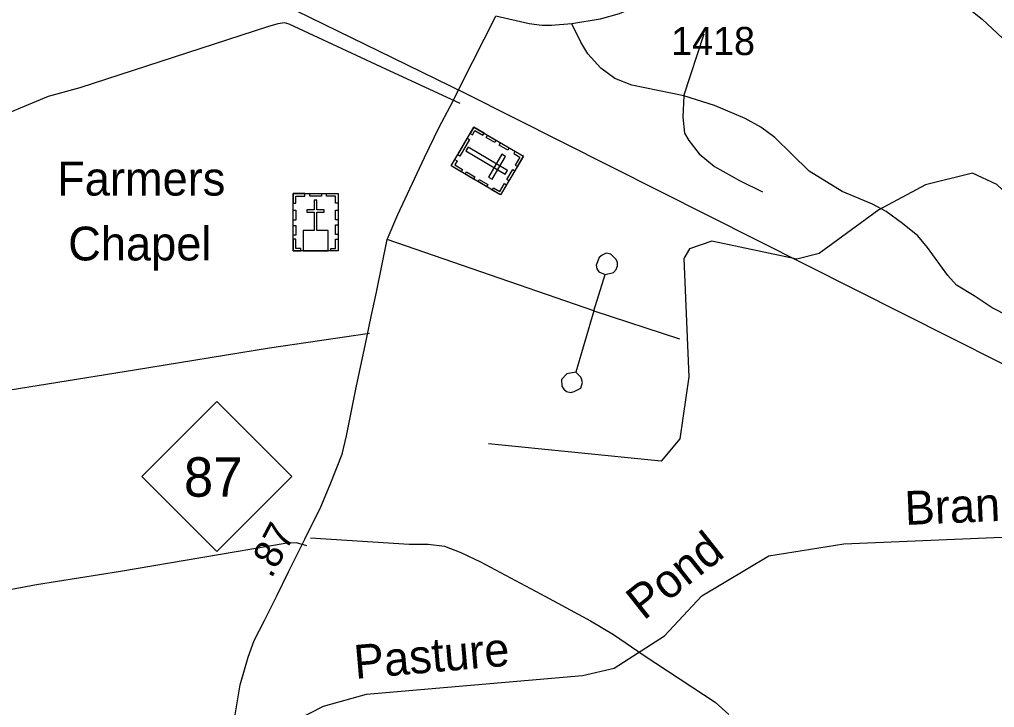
# Model space of a CAD drawing. Extents: x 2225501 to 2309677, y 165449 to 227696.
# Drawn here: x 2257649 to 2261977, y 192432 to 195485 of the extents above; entities that cross this region are included whole.
import ezdxf

# ---------------------------------------------------------------- set-up
doc = ezdxf.new("R2010")
doc.units = 0
for name, color, linetype in [('Black Area Fill Shapes', 7, 'Continuous'), ('E_RDY_CMT_EOP', 7, 'Continuous'), ('Old_Level_3', 7, 'Continuous'), ('Old_Level_33', 7, 'Continuous'), ('Old_Level_46', 7, 'Continuous'), ('Old_Level_50', 7, 'Continuous'), ('P_HYD_Endwall_838_01_48_Dia_Single-Top_CELL', 7, 'Continuous'), ('P_HYD_Junction_Box_with_Slab_Lid_840_31_15_Dia-Top_CELL', 7, 'Continuous'), ('P_HYD_RipRap_Pad_876_02_18in_Outlet_With_Ditch_CELL', 7, 'Continuous'), ('P_HYD_Table_Inlet_Data_CELL', 7, 'Continuous'), ('Prop Mkg Solid Yellow Edge Line', 7, 'Continuous'), ('Prop Support', 7, 'Continuous'), ('Scratch_Level_1', 7, 'Continuous'), ('Scratch_Level_4', 7, 'Continuous'), ('Typical Terminator CELL', 7, 'Continuous')]:
    doc.layers.add(name, color=color, linetype=linetype)

msp = doc.modelspace()

# ---------------------------------------------------------------- linework, layer by layer
at = {"layer": 'Black Area Fill Shapes'}
msp.add_lwpolyline([(2264683.4, 192626.7), (2264435.7, 192743.4), (2264161.2, 192875.9), (2259628.3, 195156.1)], dxfattribs=at)
at = {"layer": 'Old_Level_3'}
for p, q in [((2259308.7, 195312.8), (2257312.8, 196291)), ((2260598.1, 195146), (2260687.8, 195420.6)), ((2259628.3, 195156.1), (2259308.7, 195312.8)), ((2259604.7, 195111.8), (2259253.6, 195274.6)), ((2260198, 194193), (2259281.8, 194509.4)), ((2260198, 194193), (2260248.7, 194353.4)), ((2260198, 194193), (2260118.1, 193920.5)), ((2260198, 194193), (2260578.9, 194068.2))]:
    msp.add_line(p, q, dxfattribs=at)
for points in [[(2259253.6, 195274.6), (2258846.1, 195463.5), (2258826.1, 195469.5), (2258796.2, 195465), (2258750.3, 195452.7), (2257916.9, 195182.1), (2257777.1, 195143), (2257498.2, 195028.6), (2257448.5, 195012.2), (2257324.9, 194951.2), (2257231.3, 194900.5), (2257191.5, 194886.3), (2257125.4, 194899.7), (2257079.3, 194915.2), (2257051.2, 194929.2), (2257019, 194950.8), (2256991, 194962.5), (2256950.6, 195012.3), (2256883.3, 195197.4)], [(2260598.1, 195146), (2260367.7, 195194.1), (2260291.5, 195223.4), (2260229.2, 195269), (2260172.7, 195332.5), (2260140.3, 195384.1), (2260101.7, 195465.8)], [(2260598.1, 195146), (2260592.9, 195051.9), (2260601.5, 194980), (2260619.7, 194948.2), (2260666.1, 194888.6), (2260734.6, 194833.2), (2260844.9, 194770.1), (2260947.3, 194720.9)], [(2262039.5, 194168.2), (2261967.2, 194205.6), (2261886.7, 194258.9), (2261808.4, 194306.2), (2261770.1, 194349.8), (2261679.1, 194473.1), (2261636.7, 194524.7), (2261568.2, 194580), (2261495.9, 194633.4), (2261435.7, 194665), (2261301.3, 194721.8), (2261154.5, 194812.7), (2261001.4, 194961.4), (2260939.1, 195006.8), (2260870.7, 195046.3), (2260734.2, 195103.2), (2260598.1, 195146)], [(2260248.7, 194353.4), (2260286.5, 194361.7), (2260298.4, 194375.8), (2260304.3, 194391.9), (2260304.2, 194407.9), (2260296.1, 194421.9), (2260273.9, 194443.5), (2260254, 194447.5), (2260236, 194439.2), (2260222, 194429.1), (2260208.4, 194395), (2260212.4, 194379.1), (2260220.6, 194365.2), (2260248.7, 194353.4)], [(2259203.4, 194092.1), (2258759.5, 194026), (2258159.8, 193929.2), (2257560.1, 193832.4), (2257047.4, 193746.9)], [(2260118.1, 193920.5), (2260078.4, 193912.2), (2260054.5, 193888.1), (2260056.7, 193858.1), (2260064.8, 193844.1), (2260076.9, 193834.3), (2260097, 193830.5), (2260110.9, 193834.4), (2260140.7, 193848.8), (2260148.6, 193874.9), (2260144.5, 193890.7), (2260140.3, 193898.6), (2260118.1, 193920.5)], [(2258940.7, 193185.2), (2259378.5, 193157.6), (2259462.9, 193157.6), (2259535.6, 193148.9), (2259608.3, 193119.8), (2259695.5, 193079.1), (2259983.5, 192924.9), (2260184.1, 192817.2), (2260285.9, 192756.1), (2260422.6, 192663), (2260737.8, 192456.1), (2260797.9, 192401.8)], [(2258925, 193149.1), (2258878.8, 193162.8), (2258829, 193160.3), (2258098.2, 193036.4), (2257724.9, 192977.3), (2257329.5, 192902.2), (2257281.6, 192895.8), (2257138.4, 192808.6), (2257104.7, 192774.4), (2257071.3, 192702.1), (2257038.1, 192618), (2256979, 192491.4)]]:
    msp.add_lwpolyline(points, dxfattribs=at)
at = {"layer": 'Old_Level_33'}
msp.add_lwpolyline([(2261244.4, 195917), (2261128.6, 195857.3), (2260311.7, 195510.7), (2260226.7, 195487.1), (2260101.7, 195465.8), (2260011.4, 195458.2), (2259967.8, 195458.6), (2259911.7, 195466.3), (2259763.1, 195500.3)], dxfattribs=at)
at = {"layer": 'Old_Level_46'}
msp.add_lwpolyline([(2260129, 196210.1), (2260182.5, 196202.5), (2260349.2, 196183.2), (2260525.3, 196155.2), (2260707.8, 196126.2), (2260872.5, 196091.5), (2261053.4, 196046.8), (2261232.8, 195983.9), (2261407.6, 195889.4), (2261522.3, 195817.9), (2261757.7, 195618.2), (2261921.5, 195486), (2262216.4, 195210.8), (2262990.7, 194529), (2263196.2, 194348.8), (2263442, 194122.8), (2263721, 193886.9), (2263872.7, 193751), (2263970.5, 193659.8), (2264144.9, 193502.9)], dxfattribs=at)
at = {"layer": 'Old_Level_50'}
msp.add_lwpolyline([(2258595.8, 192338.5), (2258629.6, 192532.4), (2258664.3, 192655.9), (2258691.3, 192729.2), (2258737.6, 192818.2), (2258791.6, 192928.2), (2258843.7, 193034.3), (2258916, 193180), (2258987.4, 193322.8), (2259027.9, 193421.3), (2259081.9, 193556.3), (2259101.2, 193637.4), (2259145.6, 193859.3), (2259184.1, 194038.8), (2259210.2, 194167.1), (2259233.7, 194275.2), (2259281.8, 194509.4), (2259328.8, 194619.8), (2259446.5, 194872.8), (2259510.1, 195004.1), (2259562.2, 195102.5), (2259660.6, 195295.4), (2259763.1, 195500.3)], dxfattribs=at)
at = {"layer": 'P_HYD_Endwall_838_01_48_Dia_Single-Top_CELL'}
for points in [[(2258864.6, 194712.7), (2259063.7, 194712.7), (2259063.8, 194458.1), (2258864.7, 194458)], [(2258864.6, 194669.4), (2258876, 194669.4), (2258876, 194701.6), (2258916.5, 194701.6), (2258916.5, 194712.7), (2258864.6, 194712.7)], [(2258938.7, 194712.7), (2258990.5, 194712.7), (2258990.5, 194701.3), (2258938.7, 194701.3)], [(2259063.8, 194669.4), (2259052.5, 194669.4), (2259052.5, 194701.5), (2259011.9, 194701.5), (2259011.9, 194712.7), (2259063.8, 194712.7)], [(2258907.8, 194458.1), (2259019.9, 194458.1), (2259019.9, 194548.7), (2258969.2, 194548.7), (2258969.1, 194630.2), (2259002.1, 194630.2), (2259002.1, 194641.2), (2258969.1, 194641.2), (2258969.2, 194683.4), (2258957.5, 194683.4), (2258957.5, 194641.2), (2258924.4, 194641.2), (2258924.4, 194630.2), (2258957.5, 194630.2), (2258957.6, 194548.7), (2258907.8, 194548.7)], [(2258864.6, 194595.2), (2258864.6, 194638.5), (2258876, 194638.5), (2258876, 194595.2)], [(2259052.4, 194596.3), (2259052.4, 194639.6), (2259063.8, 194639.6), (2259063.8, 194596.3)], [(2258864.6, 194528), (2258864.6, 194571.3), (2258876, 194571.3), (2258876, 194528)], [(2259052.4, 194530.4), (2259052.4, 194573.7), (2259063.8, 194573.7), (2259063.8, 194530.4)], [(2258897.8, 194458.1), (2258897.8, 194469.6), (2258875.8, 194469.6), (2258875.8, 194510), (2258864.6, 194510), (2258864.6, 194458.1)], [(2259030.7, 194458.1), (2259030.7, 194469.6), (2259052.7, 194469.6), (2259052.6, 194510), (2259063.8, 194510), (2259063.8, 194458.1)]]:
    msp.add_lwpolyline(points, close=True, dxfattribs=at)
at = {"layer": 'P_HYD_Junction_Box_with_Slab_Lid_840_31_15_Dia-Top_CELL'}
msp.add_lwpolyline([(2258192, 193457.3), (2258525, 193790.3), (2258858, 193457.3), (2258525, 193124.3)], close=True, dxfattribs=at)
at = {"layer": 'Prop Mkg Solid Yellow Edge Line'}
for points in [[(2259886, 194877.9), (2259784.9, 194706.4), (2259565.5, 194835.7), (2259666.7, 195007.2)], [(2259649.9, 194978.7), (2259659.8, 194972.9), (2259671, 194991.8), (2259705.8, 194971.3), (2259711.4, 194980.9), (2259666.7, 195007.2)], [(2259647.4, 194951.9), (2259604.3, 194878.8), (2259594.5, 194884.6), (2259637.6, 194957.7)], [(2259726.9, 194971.7), (2259764.2, 194949.7), (2259758.5, 194939.9), (2259721.1, 194961.9)], [(2259805.4, 194798.9), (2259814.9, 194815), (2259640.2, 194917.9), (2259630.7, 194901.9)], [(2259784.8, 194937.6), (2259822.1, 194915.6), (2259816.4, 194905.8), (2259779, 194927.8)], [(2259806.7, 194877.3), (2259790.6, 194886.8), (2259730.8, 194785.4), (2259746.9, 194775.9)], [(2259848.7, 194899.9), (2259842.9, 194890.1), (2259870.7, 194873.8), (2259850.1, 194838.8), (2259859.6, 194833.2), (2259886, 194877.9)], [(2259582.4, 194864.3), (2259592.3, 194858.4), (2259581.1, 194839.5), (2259615.9, 194819), (2259610.3, 194809.4), (2259565.5, 194835.7)], [(2259633.6, 194808.8), (2259670.9, 194786.8), (2259665.1, 194777), (2259627.8, 194799)], [(2259848.4, 194814.1), (2259822, 194769.5), (2259812.2, 194775.2), (2259838.6, 194819.9)], [(2259690.3, 194775.3), (2259727.7, 194753.3), (2259721.9, 194743.5), (2259684.6, 194765.5)], [(2259747.5, 194728.4), (2259753.3, 194738.1), (2259781, 194721.8), (2259801.6, 194756.7), (2259811.2, 194751.1), (2259784.8, 194706.4)]]:
    msp.add_lwpolyline(points, close=True, dxfattribs=at)
at = {"layer": 'Prop Support'}
msp.add_lwpolyline([(2262848.3, 193750.5), (2262844.9, 193767.8), (2262667.7, 194066.5), (2262448.7, 194316.8), (2261986.7, 194752.2), (2261878.7, 194803.5), (2261670.8, 194751.8), (2261463.9, 194641.1), (2261198.7, 194446.1), (2261098.9, 194421.8), (2260722.8, 194501.3), (2260623.8, 194467.2), (2260598.7, 194425), (2260619.7, 193899.8), (2260580.7, 193625), (2260497.9, 193524.9), (2259730.8, 193602.1)], dxfattribs=at)
at = {"layer": 'Typical Terminator CELL'}
msp.add_lwpolyline([(2257977.8, 192055.3), (2258617.7, 192242.9), (2258998.7, 192438.9), (2259189.8, 192490.9), (2260147.8, 192573.9), (2260288.7, 192607.3), (2260512.8, 192750.5), (2260677.7, 192927.7), (2260975.8, 193105.6), (2261308.8, 193158.1), (2262466.8, 193207.8)], dxfattribs=at)

# ---------------------------------------------------------------- texts
at = {"layer": 'E_RDY_CMT_EOP'}
msp.add_text('1418', height=125, dxfattribs=at).set_placement((2260542, 195327))
at = {"layer": 'P_HYD_RipRap_Pad_876_02_18in_Outlet_With_Ditch_CELL'}
msp.add_text('87', height=175, dxfattribs=at).set_placement((2258379.1, 193367.6))
at = {"layer": 'P_HYD_Table_Inlet_Data_CELL'}
for s, p in [('Farmers', (2257816.6, 194703.8)), ('Chapel', (2257865.6, 194415.9))]:
    msp.add_text(s, height=150, dxfattribs=at).set_placement(p)
at = {"layer": 'Scratch_Level_1'}
for s, rotation, p in [('Branch', 2.4545, (2261581.2, 193242.1)), ('Pond', 38.391, (2260419.4, 192816.1)), ('Pasture', 4.9521, (2259140.2, 192559.1))]:
    msp.add_text(s, height=150, rotation=rotation, dxfattribs=at).set_placement(p)
at = {"layer": 'Scratch_Level_4'}
msp.add_text('.87', height=125, rotation=62.1305, dxfattribs=at).set_placement((2258767.9, 193001.4))

doc.saveas('drawing.dxf')
